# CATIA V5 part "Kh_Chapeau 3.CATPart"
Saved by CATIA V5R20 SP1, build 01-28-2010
Part number: Chapeau 3
Bounding box of the stored display mesh (mm): x -41.992 to 41.992, y -6 to 0, z -41.992 to 41.992
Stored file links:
  G:\Khaled_CFAO_2011\SIL\SIL_GR1\tmerino\Khaled\CAD_Thinkmotion\Kh_Chapeau 3.CATPart
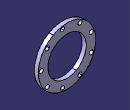
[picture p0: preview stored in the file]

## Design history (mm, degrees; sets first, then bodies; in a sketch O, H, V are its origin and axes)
Body1 (main body)
  Sketch1 on yz-plane, origin (0, 0, 0), H (0, 1, 0), V (0, 0, 1)
    line L1 (-6, -28) -> (0, -28)
    line L2 (0, -28) -> (0, -42)
    line L3 (0, -42) -> (-6, -42)
    line L4 (-6, -42) -> (-6, -28)
    distance H L1 = 28
    distance L4 L2 = 6
    distance L3 H = 42
    distance L2 V = 0
    horizontal: L1 H, L3 H
    vertical: L2 V, L4 V
  Shaft1: profile Sketch1, axis Sketch1.H, angle 360
  Sketch2 on face of Shaft1 from Sketch1.L4, origin (34.7794, -6, 7.6368), H (1, 0, 0), V (0, 0, 1)
    point P1 (3.2206, -7.6368)
    reference intersected line E1 through (0, -7.6368) direction (-1, 0) from xy-plane
    reference intersected line E2 through (-34.7794, 0) direction (0, 1) from yz-plane
    distance E1 P1 = 0
    distance E2 P1 = 38
  Hole1: placed by Sketch2, at (38, -6, 0) direction (0, 1, 0), diameter 6, through (limit type 3)
  CircPattern1: of Hole1, instances 9, angular step 40, axis from face of Shaft1 from Sketch1.L4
